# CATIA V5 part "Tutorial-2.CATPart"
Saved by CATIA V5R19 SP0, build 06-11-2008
Part number: Part1
Bounding box of the stored display mesh (mm): x -163 to 90, y -77.362 to 77.362, z -85 to 85
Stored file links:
  D:\Shriniwas\v5_r19\Part files\c09\c09_tut2.CATPart
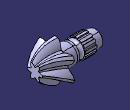
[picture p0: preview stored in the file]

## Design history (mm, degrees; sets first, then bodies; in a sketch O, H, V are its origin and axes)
Body1 (main body)
  Sketch1 on zx-plane, origin (0, 0, 0), H (-1, 0, 0), V (0, 0, 1)
    axis line L1 (-102.3376, 0) -> (234.6005, 0)
    point P1 (-102.3376, 0)
    line L2 (0, 0) -> (163, 0)
    line L3 (0, 0) -> (0, -45)
    line L4 (0, -45) -> (5, -45)
    line L5 (5, -45) -> (5, -39)
    line L6 (5, -39) -> (51, -39)
    line L7 (51, -39) -> (51, -38)
    line L8 (51, -38) -> (61, -38)
    point P10 (83, -36)
    line L9 (83, -36) -> (131, -36)
    line L10 (131, -36) -> (131, -32.5)
    line L11 (131, -32.5) -> (163, -32.5)
    line L12 (163, -32.5) -> (163, 0)
    line L13 (61, -38) -> (61, -36)
    point P14 (61, -36)
    arc A1 centre (72, -36) radius 11 from (83, -36) to (61, -36) ccw
    point P16 (61, -36)
    length L4 = 5
    "Radius" L11 L1 = 32.5
    "Radius" L4 L1 = 45
    "Radius" L6 L1 = 39
    "Radius" L8 L1 = 38
    "Radius" L9 L1 = 36
    length L6 = 46
    length L8 = 10
    length L9 = 48
    length L11 = 32
    radius A1 = 11
    distance L13 P10 = 22
    coincidence: P1 H, P16 P14
    horizontal: L1 H, L2 H, L4 H, L6 H, L8 H, L9 H, L11 H
    vertical: L3 V, L5 V, L7 V, L10 V, L12 V, L13 V
    tangency: L13 A1
  Shaft1: profile Sketch1, axis Sketch1.L1, angle 360
  Sketch2 on face of Shaft1 from Sketch1.L10, origin (-131, 0, 0), H (0, -1, 0), V (0, 0, 1)
    projected circle E1 centre (0, 0) radius 36 from edge [face of Shaft1 from Sketch1.L9 | face of Shaft1 from Sketch1.L10]
    projected arc E2 centre (0, 0) radius 36 from (5, 35.6511) to (-5, 35.6511) ccw from edge [face of Shaft1 from Sketch1.L9 | face of Shaft1 from Sketch1.L10]
    line L1 (-5, 35.6511) -> (-5, 40.6511)
    point P1 (-5, 35.6511)
    line L2 (-5, 40.6511) -> (5, 40.6511)
    line L3 (5, 40.6511) -> (5, 35.6511)
    point P4 (5, 35.6511)
    point P5 (5, 35.6511)
    length L2 = 10
    distance L1 V = 5
    length L3 = 5
    coincidence: P1 E1, L3 P4, E1 P5, P4 P5
    vertical: L1 V, L3 V
    horizontal: L2 H
  Pad1: profile Sketch2, direction (1, 0, 0), length 48
  CircPattern1: of Pad1, instances 13, angular step 27.6923 {= 360.0*1 deg/CircPattern1.AngularNumber}, axis from face of Shaft1 from Sketch1.L9
  Sketch3 on face of Shaft1 from Sketch1.L3, origin (0, 0, 0), H (0, 1, 0), V (0, 0, 1)
    arc A1 centre (0, 0) radius 50 from (-49.6863, 5.5924) to (-49.6863, -5.5924) ccw
    line L1 (-7.5, 85) -> (7.5, 85)
    point P1 (-7.5, 85)
    arc A2 centre (44.9945, 46.6682) radius 65 from (-7.5, 85) to (-20, 45.8258) ccw
    point P4 (-20, 45.8258)
    arc A3 centre (-44.9945, 46.6682) radius 65 from (20, 45.8258) to (7.5, 85) ccw
    point P6 (20, 45.8258)
    arc A4 centre (-17.9186, 62.3005) radius 65 from (-77.3622, 36.0048) to (-49.6863, 5.5924) ccw
    line L2 (-77.3622, 36.0048) -> (-69.8622, 48.9952)
    arc A5 centre (-62.9132, -15.6323) radius 65 from (-29.6863, 40.2334) to (-69.8622, 48.9952) ccw
    arc A6 centre (-62.9132, 15.6323) radius 65 from (-69.8622, -48.9952) to (-29.6863, -40.2334) ccw
    line L3 (-69.8622, -48.9952) -> (-77.3622, -36.0048)
    arc A7 centre (-17.9186, -62.3005) radius 65 from (-49.6863, -5.5924) to (-77.3622, -36.0048) ccw
    arc A8 centre (-44.9945, -46.6682) radius 65 from (7.5, -85) to (20, -45.8258) ccw
    line L4 (7.5, -85) -> (-7.5, -85)
    arc A9 centre (44.9945, -46.6682) radius 65 from (-20, -45.8258) to (-7.5, -85) ccw
    arc A10 centre (17.9186, -62.3005) radius 65 from (77.3622, -36.0048) to (49.6863, -5.5924) ccw
    line L5 (77.3622, -36.0048) -> (69.8622, -48.9952)
    arc A11 centre (62.9132, 15.6323) radius 65 from (29.6863, -40.2334) to (69.8622, -48.9952) ccw
    arc A12 centre (62.9132, -15.6323) radius 65 from (69.8622, 48.9952) to (29.6863, 40.2334) ccw
    line L6 (69.8622, 48.9952) -> (77.3622, 36.0048)
    arc A13 centre (17.9186, 62.3005) radius 65 from (49.6863, 5.5924) to (77.3622, 36.0048) ccw
    arc A14 centre (0, 0) radius 50 from (-29.6863, -40.2334) to (-20, -45.8258) ccw
    arc A15 centre (0, 0) radius 50 from (20, -45.8258) to (29.6863, -40.2334) ccw
    arc A16 centre (0, 0) radius 50 from (49.6863, -5.5924) to (49.6863, 5.5924) ccw
    arc A17 centre (0, 0) radius 50 from (29.6863, 40.2334) to (20, 45.8258) ccw
    arc A18 centre (0, 0) radius 50 from (-20, 45.8258) to (-29.6863, 40.2334) ccw
    radius A1 = 50
    length L1 = 15
    distance H L1 = 85
    distance V P1 = 7.5
    distance V P4 = 20
    distance P4 P6 H = 40
    radius A2 = 65
    radius A3 = 65
    horizontal: L1 H
    coincidence: A1 P4, A1 P6, A1 A14, A14 A15, A15 A16, A16 A17, A17 A18
  Plane1: type Offset, Offset 45, RefPlane face of Shaft1 from Sketch1.L3, reversed
  Sketch4 on Plane1, origin (45, 0, 0), H (0, -1, 0), V (0, 0, 1)
    arc A1 centre (0.0494, -0.0379) radius 37.5335 from (-29.2904, -23.446) to (-23.3588, -29.3776) ccw
    arc A2 centre (-42.517, 23.4762) radius 48.7508 from (-60.0964, -21.9947) to (-29.2904, -23.446) ccw
    line L1 (-60.0964, -21.9947) -> (-63.0081, -11.1281)
    arc A3 centre (-25.0485, -41.7174) radius 48.7508 from (-37.0549, 5.5318) to (-63.0081, -11.1281) ccw
    arc A4 centre (0.0581, -0.0704) radius 37.5335 from (-34.8838, 13.6345) to (-37.0549, 5.5318) ccw
    arc A5 centre (-0.8613, 48.5502) radius 48.7508 from (-49.03, 41.0389) to (-34.8838, 13.6345) ccw
    line L2 (-49.03, 41.0389) -> (-41.075, 48.9938)
    arc A6 centre (-48.5863, 0.8252) radius 48.7508 from (-13.6706, 34.8477) to (-41.075, 48.9938) ccw
    arc A7 centre (0.0343, -0.0942) radius 37.5335 from (-5.5679, 37.0188) to (-13.6706, 34.8477) ccw
    arc A8 centre (41.6812, 25.0123) radius 48.7508 from (11.0919, 62.9719) to (-5.5679, 37.0188) ccw
    line L3 (11.0919, 62.9719) -> (21.9586, 60.0602)
    arc A9 centre (-23.5123, 42.4809) radius 48.7508 from (23.4099, 29.2542) to (21.9586, 60.0602) ccw
    arc A10 centre (0.0017, -0.0855) radius 37.5335 from (29.3415, 23.3226) to (23.4099, 29.2542) ccw
    arc A11 centre (42.5681, -23.5996) radius 48.7508 from (60.1475, 21.8713) to (29.3415, 23.3226) ccw
    line L4 (60.1475, 21.8713) -> (63.0592, 11.0047)
    arc A12 centre (25.0996, 41.594) radius 48.7508 from (37.1061, -5.6552) to (63.0592, 11.0047) ccw
    arc A13 centre (-0.007, -0.053) radius 37.5335 from (34.9349, -13.7579) to (37.1061, -5.6552) ccw
    arc A14 centre (0.9125, -48.6736) radius 48.7508 from (49.0811, -41.1623) to (34.9349, -13.7579) ccw
    line L5 (49.0811, -41.1623) -> (41.1261, -49.1172)
    arc A15 centre (48.6375, -0.9486) radius 48.7508 from (13.7217, -34.9711) to (41.1261, -49.1172) ccw
    arc A16 centre (0.0168, -0.0292) radius 37.5335 from (5.619, -37.1422) to (13.7217, -34.9711) ccw
    arc A17 centre (-41.6301, -25.1357) radius 48.7508 from (-11.0408, -63.0953) to (5.619, -37.1422) ccw
    line L6 (-11.0408, -63.0953) -> (-21.9075, -60.1836)
    arc A18 centre (23.5634, -42.6043) radius 48.7508 from (-23.3588, -29.3776) to (-21.9075, -60.1836) ccw
  Plane2: type Offset, Offset 90, RefPlane face of Shaft1 from Sketch1.L3, reversed
  Sketch5 on Plane2, origin (90, 0, 0), H (0, -1, 0), V (0, 0, 1)
    arc A1 centre (-0.0292, -0.0168) radius 18.7835 from (17.1847, 7.5) to (15.0875, 11.1324) ccw
    arc A2 centre (-5.8629, 23.5926) radius 24.3758 from (15.0875, 11.1324) to (18.3732, 26.1983) ccw
    line L1 (18.3732, 26.1983) -> (13.5018, 29.0108)
    arc A3 centre (23.3632, 6.7189) radius 24.3758 from (13.5018, 29.0108) to (2.0971, 18.6324) ccw
    arc A4 centre (0, -0.0337) radius 18.7835 from (2.0971, 18.6324) to (-2.0971, 18.6324) ccw
    arc A5 centre (-23.3632, 6.7189) radius 24.3758 from (-2.0971, 18.6324) to (-13.5018, 29.0108) ccw
    line L2 (-13.5018, 29.0108) -> (-18.3732, 26.1983)
    arc A6 centre (5.8629, 23.5926) radius 24.3758 from (-18.3732, 26.1983) to (-15.0875, 11.1324) ccw
    arc A7 centre (0.0292, -0.0168) radius 18.7835 from (-15.0875, 11.1324) to (-17.1847, 7.5) ccw
    arc A8 centre (-17.5003, -16.8737) radius 24.3758 from (-17.1847, 7.5) to (-31.875, 2.8125) ccw
    line L3 (-31.875, 2.8125) -> (-31.875, -2.8125)
    arc A9 centre (-17.5003, 16.8737) radius 24.3758 from (-31.875, -2.8125) to (-17.1847, -7.5) ccw
    arc A10 centre (0.0292, 0.0168) radius 18.7835 from (-17.1847, -7.5) to (-15.0875, -11.1324) ccw
    arc A11 centre (5.8629, -23.5926) radius 24.3758 from (-15.0875, -11.1324) to (-18.3732, -26.1983) ccw
    line L4 (-18.3732, -26.1983) -> (-13.5018, -29.0108)
    arc A12 centre (-23.3632, -6.7189) radius 24.3758 from (-13.5018, -29.0108) to (-2.0971, -18.6324) ccw
    arc A13 centre (0, 0.0337) radius 18.7835 from (-2.0971, -18.6324) to (2.0971, -18.6324) ccw
    arc A14 centre (23.3632, -6.7189) radius 24.3758 from (2.0971, -18.6324) to (13.5018, -29.0108) ccw
    line L5 (13.5018, -29.0108) -> (18.3732, -26.1983)
    arc A15 centre (-5.8629, -23.5926) radius 24.3758 from (18.3732, -26.1983) to (15.0875, -11.1324) ccw
    arc A16 centre (-0.0292, 0.0168) radius 18.7835 from (15.0875, -11.1324) to (17.1847, -7.5) ccw
    arc A17 centre (17.5003, 16.8737) radius 24.3758 from (17.1847, -7.5) to (31.875, -2.8125) ccw
    line L6 (31.875, -2.8125) -> (31.875, 2.8125)
    arc A18 centre (17.5003, -16.8737) radius 24.3758 from (31.875, 2.8125) to (17.1847, 7.5) ccw
  Loft1: solid, Sections (Sketch3; Sketch4; Sketch5)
